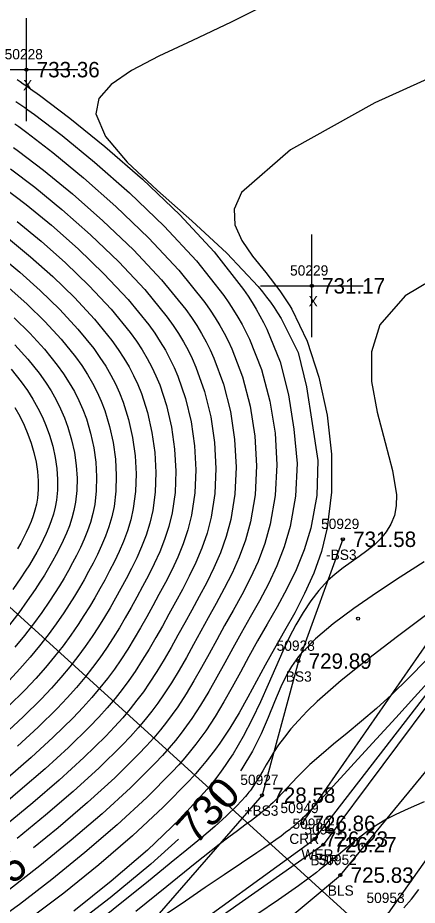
# Model space of a CAD drawing. Extents: x 1378535 to 1380697, y 997729 to 1000024.
# Drawn here: x 1379663.5 to 1379702.4, y 998964.8 to 999051.2 of the extents above; entities that cross this region are included whole.
import ezdxf

# ---------------------------------------------------------------- set-up
doc = ezdxf.new("R2010")
doc.units = 0
for name, color, linetype in [('RD_DTM_BkLn1', 7, 'Continuous'), ('RD_DTM_BkLn2', 7, 'Continuous'), ('RD_DTM_BkLn_txCode', 7, 'Continuous'), ('RD_DTM_Major1', 7, 'Continuous'), ('RD_DTM_Major1_Lbl', 7, 'Continuous'), ('RD_DTM_Minor1', 7, 'Continuous'), ('RD_EX_Bridge', 7, 'Continuous'), ('RD_EX_H2O', 7, 'Continuous'), ('RD_EX_H2O_txCode', 7, 'Continuous'), ('RD_EX_Misc', 7, 'Continuous'), ('RD_EX_Misc_txCode', 7, 'Continuous'), ('RD_EX_TX_H2O_ELEV', 7, 'Continuous'), ('RD_EX_TX_Misc_ELEV', 7, 'Continuous'), ('RD_SMD_Locator', 7, 'Continuous')]:
    doc.layers.add(name, color=color, linetype=linetype)

msp = doc.modelspace()

# ---------------------------------------------------------------- linework, layer by layer
at = {"layer": 'RD_DTM_BkLn1'}
msp.add_lwpolyline([(1379671.069, 998947.908), (1379694.884, 998967.78), (1379723.442, 999002.448), (1379771.255, 999073.041), (1379827.632, 999138.855), (1379861.249, 999179.195), (1379915.357, 999192.54), (1379973.258, 999207.681), (1380032.706, 999223.017), (1380054.696, 999270.258), (1380073.859, 999314.517)], dxfattribs=at)
at = {"layer": 'RD_DTM_BkLn2'}
for points in [[(1380068.121, 999316.651), (1380049.657, 999274.82), (1380028.513, 999225.034), (1379966.47, 999214.136), (1379918.102, 999198.529), (1379857.342, 999182.9), (1379822.296, 999142.387), (1379766.345, 999075.773), (1379728.069, 999017.429), (1379693.219, 998970.733), (1379663.886, 998950.121)], [(1380081.016, 999311.458), (1380061.411, 999264.141), (1380033.797, 999220.561), (1379978.164, 999199.192), (1379919.041, 999191.309), (1379864.05, 999174.436), (1379831.301, 999133.028), (1379774.735, 999068.751), (1379734.541, 999013.539), (1379699.544, 998964.07), (1379671.775, 998943.782)], [(1379695.125, 999000.448), (1379690.796, 998988.599), (1379687.263, 998975.552), (1379669.405, 998955.034), (1379662.246, 998951.517), (1379653.695, 998948.116)]]:
    msp.add_lwpolyline(points, dxfattribs=at)
at = {"layer": 'RD_DTM_Major1'}
for points in [[(1379663.305, 999043.039), (1379663.581, 999042.852), (1379663.866, 999042.656), (1379664.162, 999042.45), (1379664.469, 999042.232), (1379664.788, 999042.004), (1379665.12, 999041.762), (1379667.813, 999039.713), (1379670.969, 999037.134), (1379674.355, 999034.158), (1379677.737, 999030.915), (1379680.882, 999027.536), (1379683.556, 999024.152), (1379684.038, 999023.449), (1379684.491, 999022.748), (1379684.916, 999022.047), (1379685.314, 999021.341), (1379685.687, 999020.629), (1379686.037, 999019.908), (1379687.198, 999016.965), (1379688.025, 999013.899), (1379688.522, 999010.785), (1379688.693, 999007.699), (1379688.539, 999004.717), (1379688.064, 999001.914), (1379687.532, 999000.044), (1379686.87, 998998.288), (1379686.113, 998996.629), (1379685.295, 998995.049), (1379684.452, 998993.531), (1379683.619, 998992.057), (1379682.854, 998990.675), (1379682.112, 998989.318), (1379681.378, 998987.987), (1379680.633, 998986.682), (1379679.862, 998985.406), (1379679.048, 998984.157), (1379678.52, 998983.405), (1379677.961, 998982.655), (1379677.362, 998981.901), (1379676.717, 998981.135), (1379676.015, 998980.349), (1379675.25, 998979.534), (1379672.932, 998977.253), (1379670.271, 998974.834), (1379667.419, 998972.384), (1379665.03, 998970.42)], [(1379663.438, 999031.36), (1379665.75, 999029.458), (1379668.125, 999027.351), (1379670.444, 999025.113), (1379672.587, 999022.821), (1379674.437, 999020.551), (1379675.04, 999019.709), (1379675.587, 999018.873), (1379676.082, 999018.038), (1379676.529, 999017.195), (1379676.933, 999016.337), (1379677.296, 999015.457), (1379677.96, 999013.45), (1379678.447, 999011.352), (1379678.751, 999009.212), (1379678.867, 999007.078), (1379678.789, 999004.999), (1379678.511, 999003.023), (1379678.187, 999001.687), (1379677.776, 999000.42), (1379677.296, 998999.212), (1379676.765, 998998.053), (1379676.201, 998996.933), (1379675.624, 998995.843), (1379675.072, 998994.819), (1379674.518, 998993.81), (1379673.953, 998992.814), (1379673.371, 998991.827), (1379672.765, 998990.847), (1379672.128, 998989.87), (1379671.471, 998988.922), (1379670.769, 998987.97), (1379670.012, 998987.006), (1379669.19, 998986.026), (1379668.294, 998985.022), (1379667.314, 998983.991), (1379665.469, 998982.184), (1379663.447, 998980.33)], [(1379663.214, 999019.348), (1379664.458, 999017.979), (1379665.572, 999016.591), (1379666.18, 999015.735), (1379666.729, 999014.878), (1379667.22, 999014.014), (1379667.656, 999013.141), (1379668.038, 999012.256), (1379668.368, 999011.355), (1379668.73, 999010.125), (1379669.001, 999008.877), (1379669.177, 999007.629), (1379669.255, 999006.396), (1379669.234, 999005.196), (1379669.109, 999004.045), (1379668.955, 999003.255), (1379668.753, 999002.494), (1379668.508, 999001.757), (1379668.226, 999001.038), (1379667.914, 999000.332), (1379667.576, 998999.635), (1379667.234, 998998.97), (1379666.872, 998998.305), (1379666.488, 998997.634), (1379666.079, 998996.955), (1379665.643, 998996.263), (1379665.178, 998995.555), (1379664.413, 998994.447), (1379663.578, 998993.302), (1379662.671, 998992.129)], [(1379703.044, 998998.262), (1379700.696, 998996.749), (1379698.388, 998995.231), (1379696.195, 998993.722), (1379694.194, 998992.231), (1379692.461, 998990.771), (1379691.071, 998989.353), (1379690.809, 998989.035), (1379690.566, 998988.718), (1379690.34, 998988.401), (1379690.13, 998988.082), (1379689.932, 998987.76), (1379689.745, 998987.433), (1379689.08, 998986.085), (1379688.474, 998984.644), (1379687.86, 998983.12), (1379687.171, 998981.518), (1379686.34, 998979.849), (1379685.298, 998978.118), (1379685.171, 998977.932)], [(1379679.125, 998971.292), (1379676.43, 998968.854), (1379672.467, 998965.581), (1379668.537, 998962.561)]]:
    msp.add_lwpolyline(points, dxfattribs=at)
at = {"layer": 'RD_DTM_Minor1'}
for points in [[(1379692.492, 999054.906), (1379684.265, 999050.747), (1379680.489, 999048.977), (1379677.217, 999047.439), (1379674.545, 999046.044), (1379672.568, 999044.702), (1379671.38, 999043.325), (1379671.075, 999041.822), (1379672.014, 999039.632), (1379674.144, 999037.14), (1379677.08, 999034.39), (1379680.439, 999031.426), (1379683.835, 999028.291), (1379686.886, 999025.03), (1379687.297, 999024.524), (1379687.691, 999024.015), (1379688.069, 999023.502), (1379688.431, 999022.985), (1379688.777, 999022.462), (1379689.107, 999021.933), (1379690.775, 999018.625), (1379691.588, 999015.276), (1379692.134, 999011.717), (1379692.686, 999008.112), (1379692.605, 999004.704), (1379692.01, 999001.531), (1379691.365, 998999.428), (1379690.577, 998997.464), (1379689.687, 998995.619), (1379688.737, 998993.868), (1379687.769, 998992.191), (1379686.825, 998990.564), (1379685.971, 998989.037), (1379685.154, 998987.537), (1379684.349, 998986.065), (1379683.534, 998984.622), (1379682.685, 998983.208), (1379681.779, 998981.826), (1379681.315, 998981.172), (1379680.826, 998980.519), (1379680.308, 998979.862), (1379679.754, 998979.196), (1379679.159, 998978.515), (1379678.517, 998977.814), (1379676.041, 998975.324), (1379673.153, 998972.669), (1379670.015, 998969.972), (1379666.791, 998967.354), (1379663.646, 998964.937), (1379660.744, 998962.844)], [(1379708.479, 999047.543), (1379698.239, 999042.891), (1379690.025, 999038.317), (1379685.253, 999034.166), (1379684.561, 999032.551), (1379684.628, 999031.024), (1379685.28, 999029.528), (1379686.342, 999028.001), (1379687.636, 999026.387), (1379688.989, 999024.624), (1379689.189, 999024.338), (1379689.387, 999024.048), (1379689.581, 999023.752), (1379689.772, 999023.45), (1379689.96, 999023.143), (1379690.144, 999022.83), (1379691.644, 999019.706), (1379692.804, 999016.215), (1379693.601, 999012.506), (1379694.014, 999008.727), (1379694.022, 999005.027), (1379693.604, 999001.555), (1379693.036, 998999.268), (1379692.287, 998997.15), (1379691.406, 998995.172), (1379690.441, 998993.309), (1379689.445, 998991.533), (1379688.465, 998989.817), (1379687.577, 998988.211), (1379686.725, 998986.635), (1379685.882, 998985.089), (1379685.022, 998983.572), (1379684.12, 998982.084), (1379683.148, 998980.625), (1379682.721, 998980.031), (1379682.273, 998979.437), (1379681.801, 998978.84), (1379681.301, 998978.235), (1379680.768, 998977.619), (1379680.199, 998976.987), (1379677.651, 998974.383), (1379674.657, 998971.607), (1379671.377, 998968.783), (1379667.968, 998966.035), (1379664.59, 998963.487)], [(1379663.418, 999045.175), (1379663.713, 999044.972), (1379664.018, 999044.762), (1379664.331, 999044.543), (1379664.737, 999044.257), (1379664.946, 999044.108), (1379665.379, 999043.797), (1379665.604, 999043.634), (1379668.548, 999041.413), (1379671.969, 999038.652), (1379675.619, 999035.478), (1379679.25, 999032.018), (1379682.614, 999028.399), (1379685.464, 999024.746), (1379685.896, 999024.107), (1379686.304, 999023.469), (1379686.691, 999022.83), (1379687.057, 999022.188), (1379687.404, 999021.541), (1379687.732, 999020.887), (1379689.035, 999017.713), (1379689.835, 999014.486), (1379690.345, 999011.155), (1379690.689, 999007.812), (1379690.516, 999004.647), (1379689.995, 999001.682), (1379689.415, 998999.708), (1379688.698, 998997.858), (1379687.882, 998996.113), (1379687.004, 998994.453), (1379686.104, 998992.858), (1379685.218, 998991.31), (1379684.411, 998989.857), (1379683.633, 998988.429), (1379682.864, 998987.028), (1379682.086, 998985.656), (1379681.277, 998984.313), (1379680.42, 998983), (1379679.921, 998982.294), (1379679.395, 998981.59), (1379678.835, 998980.882), (1379678.232, 998980.163), (1379677.58, 998979.427), (1379676.873, 998978.666), (1379674.472, 998976.283), (1379671.694, 998973.747), (1379668.697, 998971.174), (1379665.644, 998968.678), (1379662.695, 998966.377)], [(1379663.205, 999040.85), (1379663.573, 999040.589), (1379663.961, 999040.309), (1379664.369, 999040.01), (1379666.905, 999038.059), (1379669.869, 999035.62), (1379673.043, 999032.818), (1379676.213, 999029.779), (1379679.164, 999026.63), (1379681.678, 999023.494), (1379682.202, 999022.744), (1379682.689, 999021.998), (1379683.142, 999021.252), (1379683.563, 999020.501), (1379683.954, 999019.742), (1379684.317, 999018.97), (1379685.358, 999016.239), (1379686.104, 999013.384), (1379686.556, 999010.475), (1379686.713, 999007.584), (1379686.576, 999004.783), (1379686.144, 999002.143), (1379685.656, 999000.378), (1379685.046, 998998.717), (1379684.347, 998997.145), (1379683.588, 998995.647), (1379682.802, 998994.207), (1379682.02, 998992.808), (1379681.297, 998991.497), (1379680.593, 998990.211), (1379679.892, 998988.948), (1379679.18, 998987.71), (1379678.445, 998986.496), (1379677.67, 998985.306), (1379677.114, 998984.511), (1379676.524, 998983.719), (1379675.892, 998982.922), (1379675.207, 998982.11), (1379674.46, 998981.277), (1379673.643, 998980.414), (1379671.413, 998978.231), (1379668.875, 998975.928), (1379666.169, 998973.599), (1379663.438, 998971.341)], [(1379663.077, 999038.55), (1379663.557, 999038.205), (1379665.994, 999036.352), (1379668.797, 999034.058), (1379671.776, 999031.439), (1379674.737, 999028.611), (1379677.488, 999025.691), (1379679.837, 999022.793), (1379680.392, 999022.009), (1379680.904, 999021.231), (1379681.376, 999020.452), (1379681.811, 999019.669), (1379682.212, 999018.875), (1379682.581, 999018.065), (1379683.512, 999015.531), (1379684.185, 999012.876), (1379684.595, 999010.165), (1379684.741, 999007.466), (1379684.619, 999004.845), (1379684.228, 999002.37), (1379683.783, 999000.71), (1379683.225, 998999.145), (1379682.582, 998997.663), (1379681.882, 998996.247), (1379681.153, 998994.885), (1379680.422, 998993.563), (1379679.742, 998992.324), (1379679.074, 998991.107), (1379678.407, 998989.912), (1379677.728, 998988.738), (1379677.026, 998987.585), (1379676.288, 998986.451), (1379675.706, 998985.615), (1379675.087, 998984.782), (1379674.422, 998983.942), (1379673.7, 998983.088), (1379672.912, 998982.21), (1379672.049, 998981.301), (1379669.911, 998979.214), (1379667.499, 998977.025), (1379664.941, 998974.817), (1379662.365, 998972.676)], [(1379662.776, 999036.485), (1379665.131, 999034.698), (1379667.781, 999032.527), (1379670.562, 999030.075), (1379673.307, 999027.445), (1379675.851, 999024.74), (1379678.028, 999022.063), (1379678.604, 999021.254), (1379679.132, 999020.451), (1379679.615, 999019.648), (1379680.057, 999018.839), (1379680.461, 999018.018), (1379680.831, 999017.179), (1379681.663, 999014.83), (1379682.266, 999012.366), (1379682.638, 999009.85), (1379682.773, 999007.341), (1379682.667, 999004.901), (1379682.316, 999002.591), (1379681.913, 999001.038), (1379681.406, 998999.572), (1379680.818, 998998.18), (1379680.176, 998996.849), (1379679.503, 998995.567), (1379678.824, 998994.321), (1379678.187, 998993.153), (1379677.556, 998992.006), (1379676.923, 998990.878), (1379676.276, 998989.767), (1379675.606, 998988.673), (1379674.903, 998987.592), (1379674.295, 998986.718), (1379673.648, 998985.844), (1379672.952, 998984.963), (1379672.196, 998984.066), (1379671.369, 998983.146), (1379670.463, 998982.193), (1379668.42, 998980.201), (1379666.137, 998978.124), (1379663.727, 998976.037), (1379661.306, 998974.012)], [(1379662.038, 999034.736), (1379664.287, 999033.028), (1379666.77, 999030.989), (1379669.347, 999028.709), (1379671.877, 999026.276), (1379674.218, 999023.781), (1379676.228, 999021.313), (1379676.82, 999020.485), (1379677.359, 999019.664), (1379677.85, 999018.843), (1379678.296, 999018.015), (1379678.701, 999017.173), (1379679.068, 999016.311), (1379679.811, 999014.137), (1379680.354, 999011.859), (1379680.69, 999009.532), (1379680.815, 999007.212), (1379680.724, 999004.952), (1379680.41, 999002.809), (1379680.048, 999001.364), (1379679.589, 998999.997), (1379679.056, 998998.696), (1379678.47, 998997.451), (1379677.853, 998996.249), (1379677.225, 998995.081), (1379676.63, 998993.985), (1379676.038, 998992.908), (1379675.438, 998991.846), (1379674.824, 998990.797), (1379674.186, 998989.76), (1379673.516, 998988.732), (1379672.884, 998987.82), (1379672.209, 998986.907), (1379671.482, 998985.985), (1379670.692, 998985.046), (1379669.83, 998984.083), (1379668.885, 998983.09), (1379666.94, 998981.191), (1379664.787, 998979.226), (1379662.525, 998977.258)], [(1379662.581, 999029.697), (1379664.719, 999027.937), (1379666.894, 999026.002), (1379669.006, 999023.954), (1379670.958, 999021.858), (1379672.652, 999019.777), (1379673.262, 999018.925), (1379673.814, 999018.079), (1379674.312, 999017.233), (1379674.759, 999016.378), (1379675.16, 999015.508), (1379675.518, 999014.615), (1379676.111, 999012.769), (1379676.547, 999010.847), (1379676.821, 999008.891), (1379676.928, 999006.942), (1379676.862, 999005.042), (1379676.618, 999003.233), (1379676.331, 999002.007), (1379675.966, 999000.841), (1379675.537, 998999.726), (1379675.059, 998998.655), (1379674.549, 998997.617), (1379674.022, 998996.605), (1379673.512, 998995.653), (1379672.996, 998994.713), (1379672.466, 998993.782), (1379671.917, 998992.856), (1379671.343, 998991.933), (1379670.738, 998991.007), (1379670.059, 998990.025), (1379669.329, 998989.033), (1379668.542, 998988.028), (1379667.688, 998987.006), (1379666.76, 998985.963), (1379665.748, 998984.894), (1379664.006, 998983.18), (1379662.114, 998981.436)], [(1379661.714, 999028.042), (1379663.676, 999026.425), (1379665.652, 999024.661), (1379667.563, 999022.8), (1379669.33, 999020.893), (1379670.873, 999018.994), (1379671.488, 999018.136), (1379672.042, 999017.283), (1379672.54, 999016.428), (1379672.986, 999015.565), (1379673.383, 999014.685), (1379673.735, 999013.783), (1379674.262, 999012.095), (1379674.652, 999010.345), (1379674.898, 999008.57), (1379674.997, 999006.804), (1379674.943, 999005.082), (1379674.731, 999003.44), (1379674.481, 999002.324), (1379674.159, 999001.259), (1379673.779, 999000.239), (1379673.353, 998999.255), (1379672.895, 998998.3), (1379672.416, 998997.366), (1379671.949, 998996.486), (1379671.471, 998995.615), (1379670.977, 998994.749), (1379670.462, 998993.885), (1379669.92, 998993.018), (1379669.348, 998992.145), (1379668.646, 998991.129), (1379667.889, 998990.098), (1379667.072, 998989.051), (1379666.188, 998987.987), (1379665.229, 998986.904), (1379664.189, 998985.8), (1379662.55, 998984.179)], [(1379704.94, 999026.362), (1379701.177, 999024.116), (1379698.713, 999021.324), (1379697.902, 999018.686), (1379697.914, 999015.797), (1379698.457, 999012.808), (1379699.239, 999009.872), (1379699.968, 999007.14), (1379700.351, 999004.765), (1379700.324, 999003.694), (1379700.137, 999002.75), (1379699.808, 999001.914), (1379699.356, 999001.171), (1379698.799, 999000.502), (1379698.158, 998999.891), (1379697.461, 998999.327), (1379696.717, 998998.783), (1379695.945, 998998.238), (1379695.164, 998997.673), (1379694.391, 998997.066), (1379693.645, 998996.397), (1379692.792, 998995.479), (1379691.998, 998994.453), (1379691.258, 998993.336), (1379690.562, 998992.14), (1379689.905, 998990.88), (1379689.279, 998989.571), (1379688.558, 998987.959), (1379687.842, 998986.309), (1379687.102, 998984.633), (1379686.307, 998982.944), (1379685.429, 998981.255), (1379684.439, 998979.577), (1379684.072, 998979.012), (1379683.687, 998978.448), (1379683.281, 998977.881), (1379682.851, 998977.309), (1379682.396, 998976.73), (1379681.913, 998976.141), (1379679.269, 998973.234), (1379676.119, 998970.192), (1379672.567, 998967.197), (1379668.956, 998964.271)], [(1379662.621, 999024.923), (1379664.402, 999023.327), (1379666.116, 999021.648), (1379667.703, 999019.926), (1379669.1, 999018.201), (1379669.715, 999017.341), (1379670.27, 999016.484), (1379670.767, 999015.623), (1379671.21, 999014.754), (1379671.602, 999013.869), (1379671.948, 999012.963), (1379672.416, 999011.428), (1379672.763, 999009.849), (1379672.984, 999008.252), (1379673.075, 999006.666), (1379673.032, 999005.121), (1379672.851, 999003.644), (1379672.634, 999002.638), (1379672.354, 999001.675), (1379672.022, 999000.749), (1379671.646, 998999.853), (1379671.238, 998998.981), (1379670.808, 998998.126), (1379670.383, 998997.318), (1379669.943, 998996.516), (1379669.485, 998995.715), (1379669.004, 998994.911), (1379668.496, 998994.102), (1379667.958, 998993.282), (1379667.234, 998992.233), (1379666.45, 998991.164), (1379665.603, 998990.075), (1379664.688, 998988.969), (1379663.7, 998987.847), (1379662.635, 998986.71)], [(1379663.143, 999022), (1379664.666, 999020.498), (1379666.079, 999018.955), (1379667.333, 999017.4), (1379667.946, 999016.541), (1379668.498, 999015.682), (1379668.993, 999014.819), (1379669.433, 999013.946), (1379669.82, 999013.059), (1379670.158, 999012.153), (1379670.572, 999010.771), (1379670.879, 999009.358), (1379671.076, 999007.937), (1379671.161, 999006.53), (1379671.129, 999005.158), (1379670.977, 999003.846), (1379670.793, 999002.948), (1379670.553, 999002.087), (1379670.265, 999001.255), (1379669.937, 999000.448), (1379669.578, 998999.659), (1379669.195, 998998.883), (1379668.811, 998998.147), (1379668.41, 998997.413), (1379667.989, 998996.677), (1379667.543, 998995.935), (1379667.07, 998995.184), (1379666.568, 998994.418), (1379665.823, 998993.339), (1379665.013, 998992.232), (1379664.136, 998991.101), (1379663.191, 998989.953)], [(1379662.842, 999016.996), (1379663.82, 999015.771), (1379664.42, 999014.925), (1379664.963, 999014.071), (1379665.45, 999013.21), (1379665.88, 999012.341), (1379666.256, 999011.462), (1379666.578, 999010.572), (1379666.893, 999009.492), (1379667.129, 999008.407), (1379667.285, 999007.329), (1379667.358, 999006.267), (1379667.346, 999005.235), (1379667.247, 999004.242), (1379667.122, 999003.558), (1379666.955, 999002.896), (1379666.75, 999002.252), (1379666.512, 999001.62), (1379666.244, 999000.997), (1379665.951, 999000.379), (1379665.649, 998999.786), (1379665.327, 998999.19), (1379664.981, 998998.585), (1379664.611, 998997.97), (1379664.214, 998997.34), (1379663.788, 998996.692), (1379663.007, 998995.557)], [(1379663.203, 999013.263), (1379663.684, 999012.408), (1379664.109, 999011.546), (1379664.478, 999010.678), (1379664.791, 999009.805), (1379665.061, 999008.877), (1379665.265, 999007.953), (1379665.402, 999007.04), (1379665.469, 999006.145), (1379665.466, 999005.275), (1379665.391, 999004.436), (1379665.292, 999003.856), (1379665.158, 999003.291), (1379664.99, 999002.738), (1379664.792, 999002.193), (1379664.567, 999001.652), (1379664.317, 999001.112), (1379664.056, 999000.591), (1379663.773, 999000.064), (1379663.467, 998999.528)], [(1379703.162, 998993.03), (1379700.447, 998991), (1379697.647, 998988.856), (1379694.971, 998986.706), (1379692.627, 998984.656), (1379691.662, 998983.722), (1379690.814, 998982.836), (1379690.074, 998981.994), (1379689.431, 998981.195), (1379688.873, 998980.438), (1379688.391, 998979.719), (1379688.01, 998979.1), (1379687.665, 998978.506), (1379687.338, 998977.931), (1379687.012, 998977.368), (1379686.67, 998976.812), (1379686.295, 998976.258), (1379686.196, 998976.123), (1379686.095, 998975.987), (1379685.99, 998975.851), (1379685.882, 998975.714), (1379685.77, 998975.576), (1379685.654, 998975.438), (1379684.809, 998974.513), (1379683.806, 998973.538), (1379682.655, 998972.506), (1379681.366, 998971.41), (1379679.948, 998970.241), (1379678.41, 998968.991), (1379676.005, 998967.044), (1379673.464, 998964.993), (1379670.883, 998962.918)], [(1379703.225, 998988.68), (1379701.551, 998986.957), (1379699.86, 998985.322), (1379698.388, 998983.994), (1379696.94, 998982.753), (1379695.543, 998981.594), (1379694.224, 998980.507), (1379693.01, 998979.487), (1379691.926, 998978.526), (1379691.293, 998977.923), (1379690.718, 998977.343), (1379690.192, 998976.791), (1379689.247, 998975.773), (1379688.809, 998975.312), (1379688.571, 998975.071), (1379688.334, 998974.84), (1379688.095, 998974.615), (1379687.852, 998974.395), (1379687.603, 998974.178), (1379687.344, 998973.962), (1379686.819, 998973.546), (1379686.24, 998973.108), (1379685.592, 998972.63), (1379684.861, 998972.092), (1379684.034, 998971.477), (1379683.096, 998970.764), (1379680.736, 998968.909), (1379677.981, 998966.688), (1379674.99, 998964.251)], [(1379703.397, 998986.516), (1379702.087, 998985.081), (1379700.267, 998983.079), (1379698.41, 998981.035), (1379696.597, 998979.043), (1379694.907, 998977.197), (1379693.42, 998975.591), (1379692.216, 998974.319), (1379691.928, 998974.023), (1379691.666, 998973.759), (1379691.425, 998973.521), (1379691.201, 998973.306), (1379690.989, 998973.107), (1379690.784, 998972.921), (1379690.65, 998972.803), (1379690.517, 998972.687), (1379690.382, 998972.572), (1379690.245, 998972.458), (1379690.105, 998972.343), (1379689.961, 998972.227), (1379689.556, 998971.911), (1379689.108, 998971.575), (1379688.61, 998971.214), (1379688.057, 998970.823), (1379687.443, 998970.397), (1379686.76, 998969.932), (1379685.27, 998968.933), (1379683.573, 998967.802), (1379681.73, 998966.568), (1379679.8, 998965.259), (1379677.845, 998963.902)], [(1379703.041, 998974.903), (1379702.077, 998974.48), (1379701.135, 998974.071), (1379700.228, 998973.658), (1379699.37, 998973.225), (1379698.45, 998972.684), (1379697.59, 998972.099), (1379696.766, 998971.473), (1379695.953, 998970.812), (1379695.129, 998970.121), (1379694.269, 998969.402), (1379694.001, 998969.183), (1379693.727, 998968.961), (1379693.447, 998968.736), (1379693.159, 998968.508), (1379692.863, 998968.278), (1379692.559, 998968.044), (1379690.812, 998966.752), (1379688.861, 998965.379), (1379686.761, 998963.948)], [(1379701.074, 998964.597), (1379701.797, 998965.455), (1379702.508, 998966.374)]]:
    msp.add_lwpolyline(points, dxfattribs=at)
at = {"layer": 'RD_EX_Bridge'}
msp.add_lwpolyline([(1379637.224, 998986.549), (1379644.844, 998995.13), (1379652.407, 999003.171), (1379729.964, 998932.802)], dxfattribs=at)
at = {"layer": 'RD_EX_H2O'}
for points in [[(1379663.754, 998950.515), (1379692.381, 998971.287), (1379719.043, 999005.745), (1379767.054, 999077.466), (1379820.322, 999142.061), (1379856.776, 999184.172), (1379909.653, 999199.365), (1379968.411, 999216.307), (1380029.427, 999227.408), (1380049.406, 999276.128), (1380067.001, 999316.436)], [(1379691.169, 998972.812), (1379715.491, 999007.823), (1379758.477, 999085.154), (1379818.066, 999143.325), (1379854.662, 999185.612), (1379907.498, 999203.656)]]:
    msp.add_lwpolyline(points, dxfattribs=at)
at = {"layer": 'RD_EX_Misc'}
for p, q in [((1379664.325, 999041.134), (1379664.325, 999051.134)), ((1379659.325, 999046.134), (1379669.325, 999046.134)), ((1379692.106, 999020.099), (1379692.106, 999030.099)), ((1379687.106, 999025.099), (1379697.106, 999025.099))]:
    msp.add_line(p, q, dxfattribs=at)
at = {"layer": 'RD_SMD_Locator'}
for centre in [(1379664.325, 999046.134), (1379692.106, 999025.099), (1379695.125, 999000.448), (1379695.125, 999000.448), (1379696.611, 998992.73), (1379690.796, 998988.599), (1379687.263, 998975.552), (1379691.169, 998972.812), (1379692.381, 998971.287), (1379692.381, 998971.287), (1379693.219, 998970.733), (1379694.884, 998967.78), (1379694.884, 998967.78)]:
    msp.add_circle(centre, 0.15, dxfattribs=at)

# ---------------------------------------------------------------- texts
at = {"layer": 'RD_DTM_BkLn_txCode'}
for s, p in [('50929', (1379693.007, 999001.448)), ('50929', (1379693.007, 999001.448)), ('-BS3', (1379693.487, 998998.448)), ('-BS3', (1379693.487, 998998.448)), ('50928', (1379688.678, 998989.599)), ('BS3', (1379689.568, 998986.599)), ('50927', (1379685.145, 998976.552)), ('+BS3', (1379685.546, 998973.552)), ('50951', (1379691.384, 998971.733)), ('BSR', (1379691.967, 998968.733)), ('50952', (1379692.766, 998968.78)), ('50952', (1379692.766, 998968.78)), ('BLS', (1379693.656, 998965.78)), ('BLS', (1379693.656, 998965.78)), ('50953', (1379697.426, 998965.07))]:
    msp.add_text(s, height=1, dxfattribs=at).set_placement(p)
at = {"layer": 'RD_DTM_Major1_Lbl'}
for s, rotation, p in [('730', 47.68134, (1379680.828, 998970.61)), ('735', 37.60337, (1379659.369, 998964.087))]:
    msp.add_text(s, height=3, rotation=rotation, dxfattribs=at).set_placement(p)
at = {"layer": 'RD_EX_H2O_txCode'}
for s, p in [('50949', (1379689.051, 998973.812)), ('50950', (1379690.224, 998972.287)), ('50950', (1379690.224, 998972.287)), ('CRR', (1379689.917, 998970.812)), ('WER', (1379691.09, 998969.287)), ('WER', (1379691.09, 998969.287))]:
    msp.add_text(s, height=1, dxfattribs=at).set_placement(p)
at = {"layer": 'RD_EX_Misc_txCode'}
for s, p in [('50228', (1379662.207, 999047.134)), ('X', (1379664.01, 999044.134)), ('50229', (1379689.988, 999026.099)), ('X', (1379691.791, 999023.099))]:
    msp.add_text(s, height=1, dxfattribs=at).set_placement(p)
at = {"layer": 'RD_EX_TX_H2O_ELEV'}
for s, p in [('726.86', (1379692.169, 998972.062)), ('726.23', (1379693.381, 998970.537)), ('726.23', (1379693.381, 998970.537))]:
    msp.add_text(s, height=1.5, dxfattribs=at).set_placement(p)
at = {"layer": 'RD_EX_TX_Misc_ELEV'}
for s, p in [('733.36', (1379665.325, 999045.384)), ('731.17', (1379693.106, 999024.349)), ('731.58', (1379696.125, 998999.698)), ('731.58', (1379696.125, 998999.698)), ('729.89', (1379691.796, 998987.849)), ('728.58', (1379688.263, 998974.802)), ('726.27', (1379694.219, 998969.983)), ('725.83', (1379695.884, 998967.03)), ('725.83', (1379695.884, 998967.03))]:
    msp.add_text(s, height=1.5, dxfattribs=at).set_placement(p)

doc.saveas('drawing.dxf')
